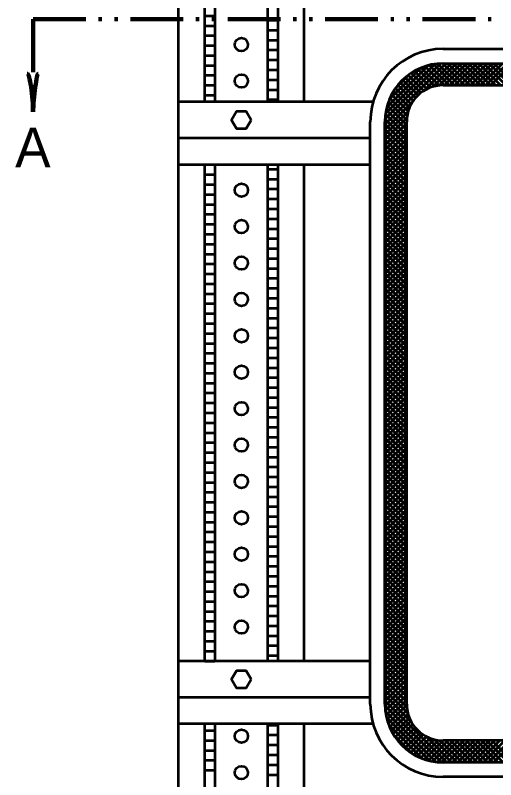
# Model space of a CAD drawing. Extents: x -87 to 768, y -466 to 78.
# Drawn here: x 252.4 to 296, y -292.3 to -223 of the extents above; entities that cross this region are included whole.
import ezdxf
from ezdxf.enums import TextEntityAlignment as Align

# ---------------------------------------------------------------- set-up
doc = ezdxf.new("R2010")
doc.units = 0
doc.header["$LTSCALE"] = 0.96
doc.linetypes.add('DASH_DOUBLE_DOT', pattern=[9.2, 5, -1.2, 0.3, -1.2, 0.3, -1.2])
doc.layers.add('1', color=7, linetype='Continuous', lineweight=53)

msp = doc.modelspace()

# ---------------------------------------------------------------- linework, layer by layer
at = {"layer": '1'}
for p, q in [((267.1887, -317.295), (267.1887, -172.4594)), ((269.5887, -230.895), (269.5887, -174.8594)), ((270.4887, -175.7593), (270.4887, -230.895)), ((275.2887, -230.895), (275.2887, -180.5593)), ((276.1887, -181.4593), (276.1887, -230.895)), ((278.5887, -230.895), (278.5887, -183.8593)), ((269.5887, -223.089), (270.4887, -223.089)), ((275.2887, -223.4938), (276.1887, -223.4938)), ((269.5887, -223.989), (270.4887, -223.989)), ((275.2887, -224.3938), (276.1887, -224.3938)), ((269.5887, -224.889), (270.4887, -224.889)), ((269.5887, -225.789), (270.4887, -225.789)), ((275.2887, -225.2938), (276.1887, -225.2938)), ((275.2887, -226.1938), (276.1887, -226.1938)), ((291.1887, -226.095), (343.9887, -226.095)), ((269.5887, -226.689), (270.4887, -226.689)), ((275.2887, -227.0938), (276.1887, -227.0938)), ((269.5887, -227.589), (270.4887, -227.589)), ((275.2887, -227.9938), (276.1887, -227.9938)), ((285.9087, -232.9502), (291.4439, -227.415)), ((285.9165, -232.4756), (290.9694, -227.4227)), ((285.9598, -231.9655), (290.4571, -227.4684)), ((286.0783, -231.3805), (289.8745, -227.5842)), ((286.3117, -230.6803), (289.1748, -227.8172)), ((290.4321, -229.4832), (288.8917, -227.9427)), ((290.8328, -229.4172), (289.2155, -227.7998)), ((289.4043, -229.9212), (291.9105, -227.415)), ((291.2772, -229.395), (289.5578, -227.6755)), ((291.744, -229.395), (289.9207, -227.5718)), ((290.2609, -229.5312), (292.3772, -227.415)), ((292.2107, -229.395), (290.3066, -227.491)), ((292.6773, -229.395), (290.7189, -227.4365)), ((290.8425, -229.4163), (292.8438, -227.415)), ((293.144, -229.395), (291.1643, -227.4152)), ((291.1887, -227.415), (343.9887, -227.415)), ((291.3306, -229.395), (293.3106, -227.415)), ((293.6107, -229.395), (291.6307, -227.415)), ((291.7973, -229.395), (293.7773, -227.415)), ((294.0774, -229.395), (292.0974, -227.415)), ((292.2639, -229.395), (294.2439, -227.415)), ((294.5441, -229.395), (292.5641, -227.415)), ((292.7307, -229.395), (294.7107, -227.415)), ((295.0107, -229.395), (293.0307, -227.415)), ((293.1974, -229.395), (295.1774, -227.415)), ((295.4775, -229.395), (293.4975, -227.415)), ((293.664, -229.395), (295.644, -227.415)), ((295.9442, -229.395), (293.9642, -227.415)), ((294.1307, -229.395), (296.1107, -227.415)), ((296.4108, -229.395), (294.4308, -227.415)), ((294.5975, -229.395), (296.5775, -227.415)), ((296.8775, -229.395), (294.8975, -227.415)), ((295.0641, -229.395), (297.0441, -227.415)), ((297.3443, -229.395), (295.3643, -227.415)), ((295.5308, -229.395), (297.5108, -227.415)), ((297.8109, -229.395), (295.8309, -227.415)), ((269.5887, -228.489), (270.4887, -228.489)), ((286.8856, -229.6398), (288.1306, -228.3947)), ((289.1695, -230.0874), (287.7626, -228.6804)), ((289.4453, -229.8964), (288.0211, -228.4723)), ((289.7461, -229.7306), (288.2945, -228.279)), ((290.074, -229.5919), (288.585, -228.1027)), ((275.2887, -228.8938), (276.1887, -228.8938)), ((288.6896, -230.5408), (287.289, -229.1402)), ((288.9175, -230.302), (287.5186, -228.9031)), ((269.5887, -229.389), (270.4887, -229.389)), ((275.2887, -229.7938), (276.1887, -229.7938)), ((288.1545, -231.4058), (286.6877, -229.939)), ((288.3074, -231.092), (286.8732, -229.6577)), ((288.4863, -230.8043), (287.0738, -229.3917)), ((291.1887, -229.395), (343.9887, -229.395)), ((269.5887, -230.289), (270.4887, -230.289)), ((275.2887, -230.6938), (276.1887, -230.6938)), ((287.9392, -232.1238), (286.3652, -230.5498)), ((288.03, -231.7481), (286.5181, -230.236)), ((284.8389, -230.895), (267.1887, -230.895)), ((285.9087, -233.4168), (288.4194, -230.906)), ((287.8887, -233.0067), (286.1154, -231.2335)), ((287.8953, -232.5467), (286.2303, -230.8817)), ((285.9087, -233.8835), (288.0233, -231.7688)), ((287.8887, -233.9402), (285.9554, -232.0069)), ((287.8887, -233.4734), (286.0227, -231.6075)), ((284.5887, -285.495), (284.5887, -232.695)), ((285.9087, -234.3501), (287.9086, -232.3502)), ((285.9087, -285.495), (285.9087, -232.695)), ((285.9087, -234.8169), (287.8887, -232.8369)), ((287.8887, -234.4068), (285.9178, -232.436)), ((287.8887, -285.495), (287.8887, -232.695)), ((287.8887, -234.8735), (285.9087, -232.8935)), ((285.9087, -235.2836), (287.8887, -233.3036)), ((287.8887, -235.3402), (285.9087, -233.3602)), ((284.5887, -234.195), (267.1887, -234.195)), ((285.9087, -235.7502), (287.8887, -233.7702)), ((287.8887, -235.8069), (285.9087, -233.8269)), ((285.9087, -236.2169), (287.8887, -234.2369)), ((287.8887, -236.2736), (285.9087, -234.2936)), ((285.9087, -236.6837), (287.8887, -234.7037)), ((287.8887, -236.7402), (285.9087, -234.7602)), ((285.9087, -237.1503), (287.8887, -235.1703)), ((287.8887, -237.2069), (285.9087, -235.2269)), ((285.9087, -237.617), (287.8887, -235.637)), ((287.8887, -237.6737), (285.9087, -235.6937)), ((285.9087, -238.0837), (287.8887, -236.1037)), ((287.8887, -238.1403), (285.9087, -236.1603)), ((284.5887, -236.595), (267.1887, -236.595)), ((269.5887, -281.595), (269.5887, -236.595)), ((270.4887, -236.595), (270.4887, -281.595)), ((275.2887, -281.595), (275.2887, -236.595)), ((275.2887, -236.9938), (276.1887, -236.9938)), ((276.1887, -236.595), (276.1887, -281.595)), ((278.5887, -281.595), (278.5887, -236.595)), ((285.9087, -238.5504), (287.8887, -236.5704)), ((287.8887, -238.607), (285.9087, -236.627)), ((269.5887, -237.489), (270.4887, -237.489)), ((285.9087, -239.0171), (287.8887, -237.0371)), ((287.8887, -239.0737), (285.9087, -237.0937)), ((285.9087, -239.4838), (287.8887, -237.5038)), ((287.8887, -239.5404), (285.9087, -237.5604)), ((269.5887, -238.389), (270.4887, -238.389)), ((275.2887, -237.8938), (276.1887, -237.8938)), ((285.9087, -239.9504), (287.8887, -237.9704)), ((287.8887, -240.0071), (285.9087, -238.0271)), ((275.2887, -238.7938), (276.1887, -238.7938)), ((285.9087, -240.4172), (287.8887, -238.4372)), ((287.8887, -240.4738), (285.9087, -238.4938)), ((285.9087, -240.8838), (287.8887, -238.9038)), ((287.8887, -240.9404), (285.9087, -238.9604)), ((269.5887, -239.289), (270.4887, -239.289)), ((275.2887, -239.6938), (276.1887, -239.6938)), ((285.9087, -241.3505), (287.8887, -239.3705)), ((287.8887, -241.4072), (285.9087, -239.4272)), ((269.5887, -240.189), (270.4887, -240.189)), ((285.9087, -241.8173), (287.8887, -239.8373)), ((287.8887, -241.8739), (285.9087, -239.8939)), ((285.9087, -242.2839), (287.8887, -240.3039)), ((287.8887, -242.3405), (285.9087, -240.3605)), ((269.5887, -241.089), (270.4887, -241.089)), ((275.2887, -240.5938), (276.1887, -240.5938)), ((285.9087, -242.7506), (287.8887, -240.7706)), ((287.8887, -242.8073), (285.9087, -240.8273)), ((275.2887, -241.4938), (276.1887, -241.4938)), ((285.9087, -243.2173), (287.8887, -241.2373)), ((287.8887, -243.2739), (285.9087, -241.2939)), ((285.9087, -243.684), (287.8887, -241.704)), ((287.8887, -243.7406), (285.9087, -241.7606)), ((269.5887, -241.989), (270.4887, -241.989)), ((275.2887, -242.3938), (276.1887, -242.3938)), ((285.9087, -244.1507), (287.8887, -242.1707)), ((287.8887, -244.2073), (285.9087, -242.2273)), ((269.5887, -242.889), (270.4887, -242.889)), ((285.9087, -244.6174), (287.8887, -242.6374)), ((287.8887, -244.674), (285.9087, -242.694)), ((285.9087, -245.084), (287.8887, -243.104)), ((287.8887, -245.1407), (285.9087, -243.1607)), ((269.5887, -243.789), (270.4887, -243.789)), ((275.2887, -243.2938), (276.1887, -243.2938)), ((285.9087, -245.5508), (287.8887, -243.5708)), ((287.8887, -245.6074), (285.9087, -243.6274)), ((275.2887, -244.1938), (276.1887, -244.1938)), ((285.9087, -246.0174), (287.8887, -244.0374)), ((287.8887, -246.074), (285.9087, -244.094)), ((285.9087, -246.4841), (287.8887, -244.5041)), ((287.8887, -246.5408), (285.9087, -244.5608)), ((269.5887, -244.689), (270.4887, -244.689)), ((275.2887, -245.0938), (276.1887, -245.0938)), ((285.9087, -246.9508), (287.8887, -244.9708)), ((287.8887, -247.0075), (285.9087, -245.0275)), ((269.5887, -245.589), (270.4887, -245.589)), ((275.2887, -245.9938), (276.1887, -245.9938)), ((285.9087, -247.4175), (287.8887, -245.4375)), ((287.8887, -247.4741), (285.9087, -245.4941)), ((285.9087, -247.8842), (287.8887, -245.9042)), ((287.8887, -247.9408), (285.9087, -245.9608)), ((269.5887, -246.489), (270.4887, -246.489)), ((285.9087, -248.3509), (287.8887, -246.3709)), ((287.8887, -248.4075), (285.9087, -246.4275)), ((269.5887, -247.389), (270.4887, -247.389)), ((275.2887, -246.8938), (276.1887, -246.8938)), ((285.9087, -248.8175), (287.8887, -246.8375)), ((287.8887, -248.8742), (285.9087, -246.8942)), ((285.9087, -249.2843), (287.8887, -247.3043)), ((287.8887, -249.3409), (285.9087, -247.3609)), ((275.2887, -247.7938), (276.1887, -247.7938)), ((285.9087, -249.751), (287.8887, -247.771)), ((287.8887, -249.8075), (285.9087, -247.8275)), ((269.5887, -248.289), (270.4887, -248.289)), ((275.2887, -248.6938), (276.1887, -248.6938)), ((285.9087, -250.2176), (287.8887, -248.2376)), ((287.8887, -250.2743), (285.9087, -248.2943)), ((285.9087, -250.6844), (287.8887, -248.7044)), ((287.8887, -250.741), (285.9087, -248.761)), ((269.5887, -249.189), (270.4887, -249.189)), ((285.9087, -251.1511), (287.8887, -249.1711)), ((287.8887, -251.2076), (285.9087, -249.2276)), ((269.5887, -250.089), (270.4887, -250.089)), ((275.2887, -249.5938), (276.1887, -249.5938)), ((285.9087, -251.6177), (287.8887, -249.6377)), ((287.8887, -251.6744), (285.9087, -249.6944)), ((285.9087, -252.0844), (287.8887, -250.1044)), ((287.8887, -252.1411), (285.9087, -250.1611)), ((275.2887, -250.4938), (276.1887, -250.4938)), ((285.9087, -252.5511), (287.8887, -250.5711)), ((287.8887, -252.6077), (285.9087, -250.6277)), ((269.5887, -250.989), (270.4887, -250.989)), ((275.2887, -251.3938), (276.1887, -251.3938)), ((285.9087, -253.0178), (287.8887, -251.0378)), ((287.8887, -253.0744), (285.9087, -251.0944)), ((285.9087, -253.4845), (287.8887, -251.5045)), ((269.5887, -251.889), (270.4887, -251.889)), ((287.8887, -253.5412), (285.9087, -251.5612)), ((285.9087, -253.9511), (287.8887, -251.9711)), ((287.8887, -254.0078), (285.9087, -252.0278)), ((269.5887, -252.789), (270.4887, -252.789)), ((275.2887, -252.2938), (276.1887, -252.2938)), ((285.9087, -254.4179), (287.8887, -252.4379)), ((287.8887, -254.4745), (285.9087, -252.4945)), ((285.9087, -254.8846), (287.8887, -252.9046)), ((275.2887, -253.1938), (276.1887, -253.1938)), ((287.8887, -254.9411), (285.9087, -252.9611)), ((285.9087, -255.3512), (287.8887, -253.3712)), ((287.8887, -255.4079), (285.9087, -253.4279)), ((269.5887, -253.689), (270.4887, -253.689)), ((275.2887, -254.0938), (276.1887, -254.0938)), ((285.9087, -255.8179), (287.8887, -253.8379)), ((287.8887, -255.8746), (285.9087, -253.8946)), ((285.9087, -256.2847), (287.8887, -254.3047)), ((269.5887, -254.589), (270.4887, -254.589)), ((275.2887, -254.9938), (276.1887, -254.9938)), ((287.8887, -256.3412), (285.9087, -254.3612)), ((285.9087, -256.7513), (287.8887, -254.7713)), ((287.8887, -256.8079), (285.9087, -254.8279)), ((269.5887, -255.489), (270.4887, -255.489)), ((285.9087, -257.218), (287.8887, -255.238)), ((287.8887, -257.2747), (285.9087, -255.2947)), ((285.9087, -257.6846), (287.8887, -255.7046)), ((269.5887, -256.389), (270.4887, -256.389)), ((275.2887, -255.8938), (276.1887, -255.8938)), ((287.8887, -257.7413), (285.9087, -255.7613)), ((285.9087, -258.1514), (287.8887, -256.1714)), ((287.8887, -258.208), (285.9087, -256.228)), ((275.2887, -256.7938), (276.1887, -256.7938)), ((285.9087, -258.6181), (287.8887, -256.6381)), ((287.8887, -258.6748), (285.9087, -256.6948)), ((269.5887, -257.289), (270.4887, -257.289)), ((275.2887, -257.6938), (276.1887, -257.6938)), ((285.9087, -259.0847), (287.8887, -257.1047)), ((287.8887, -259.1414), (285.9087, -257.1614)), ((285.9087, -259.5515), (287.8887, -257.5715)), ((287.8887, -259.6081), (285.9087, -257.6281)), ((269.5887, -258.189), (270.4887, -258.189)), ((285.9087, -260.0182), (287.8887, -258.0382)), ((287.8887, -260.0747), (285.9087, -258.0947)), ((269.5887, -259.089), (270.4887, -259.089)), ((275.2887, -258.5938), (276.1887, -258.5938)), ((285.9087, -260.4848), (287.8887, -258.5048)), ((287.8887, -260.5415), (285.9087, -258.5615)), ((285.9087, -260.9515), (287.8887, -258.9715)), ((287.8887, -261.0082), (285.9087, -259.0282)), ((275.2887, -259.4938), (276.1887, -259.4938)), ((285.9087, -261.4183), (287.8887, -259.4383)), ((287.8887, -261.4748), (285.9087, -259.4948)), ((269.5887, -259.989), (270.4887, -259.989)), ((275.2887, -260.3938), (276.1887, -260.3938)), ((285.9087, -261.8849), (287.8887, -259.9049)), ((287.8887, -261.9415), (285.9087, -259.9615)), ((285.9087, -262.3516), (287.8887, -260.3716)), ((287.8887, -262.4083), (285.9087, -260.4283)), ((269.5887, -260.889), (270.4887, -260.889)), ((285.9087, -262.8183), (287.8887, -260.8383)), ((287.8887, -262.8749), (285.9087, -260.8949)), ((269.5887, -261.789), (270.4887, -261.789)), ((275.2887, -261.2938), (276.1887, -261.2938)), ((285.9087, -263.285), (287.8887, -261.305)), ((287.8887, -263.3416), (285.9087, -261.3616)), ((285.9087, -263.7517), (287.8887, -261.7717)), ((287.8887, -263.8083), (285.9087, -261.8283)), ((275.2887, -262.1938), (276.1887, -262.1938)), ((285.9087, -264.2183), (287.8887, -262.2383)), ((287.8887, -264.275), (285.9087, -262.295)), ((269.5887, -262.689), (270.4887, -262.689)), ((275.2887, -263.0938), (276.1887, -263.0938)), ((285.9087, -264.685), (287.8887, -262.705)), ((287.8887, -264.7417), (285.9087, -262.7617)), ((285.9087, -265.1518), (287.8887, -263.1718)), ((287.8887, -265.2084), (285.9087, -263.2284)), ((269.5887, -263.589), (270.4887, -263.589)), ((275.2887, -263.9938), (276.1887, -263.9938)), ((285.9087, -265.6184), (287.8887, -263.6384)), ((287.8887, -265.675), (285.9087, -263.695)), ((269.5887, -264.489), (270.4887, -264.489)), ((285.9087, -266.0851), (287.8887, -264.1051)), ((287.8887, -266.1418), (285.9087, -264.1618)), ((285.9087, -266.5519), (287.8887, -264.5719)), ((287.8887, -266.6084), (285.9087, -264.6284)), ((269.5887, -265.389), (270.4887, -265.389)), ((275.2887, -264.8938), (276.1887, -264.8938)), ((285.9087, -267.0185), (287.8887, -265.0385)), ((287.8887, -267.0751), (285.9087, -265.0951)), ((275.2887, -265.7938), (276.1887, -265.7938)), ((285.9087, -267.4852), (287.8887, -265.5052)), ((287.8887, -267.5419), (285.9087, -265.5619)), ((285.9087, -267.9519), (287.8887, -265.9719)), ((287.8887, -268.0085), (285.9087, -266.0285)), ((269.5887, -266.289), (270.4887, -266.289)), ((275.2887, -266.6938), (276.1887, -266.6938)), ((285.9087, -268.4186), (287.8887, -266.4386)), ((287.8887, -268.4752), (285.9087, -266.4952)), ((269.5887, -267.189), (270.4887, -267.189)), ((285.9087, -268.8853), (287.8887, -266.9053)), ((287.8887, -268.9419), (285.9087, -266.9619)), ((285.9087, -269.352), (287.8887, -267.372)), ((287.8887, -269.4086), (285.9087, -267.4286)), ((269.5887, -268.089), (270.4887, -268.089)), ((275.2887, -267.5938), (276.1887, -267.5938)), ((285.9087, -269.8186), (287.8887, -267.8386)), ((287.8887, -269.8753), (285.9087, -267.8953)), ((275.2887, -268.4938), (276.1887, -268.4938)), ((285.9087, -270.2854), (287.8887, -268.3054)), ((287.8887, -270.342), (285.9087, -268.362)), ((285.9087, -270.752), (287.8887, -268.772)), ((287.8887, -270.8086), (285.9087, -268.8286)), ((269.5887, -268.989), (270.4887, -268.989)), ((275.2887, -269.3938), (276.1887, -269.3938)), ((285.9087, -271.2187), (287.8887, -269.2387)), ((287.8887, -271.2754), (285.9087, -269.2954)), ((269.5887, -269.889), (270.4887, -269.889)), ((285.9087, -271.6854), (287.8887, -269.7054)), ((287.8887, -271.7421), (285.9087, -269.7621)), ((285.9087, -272.1521), (287.8887, -270.1721)), ((287.8887, -272.2087), (285.9087, -270.2287)), ((269.5887, -270.789), (270.4887, -270.789)), ((275.2887, -270.2938), (276.1887, -270.2938)), ((285.9087, -272.6188), (287.8887, -270.6388)), ((287.8887, -272.6754), (285.9087, -270.6954)), ((275.2887, -271.1938), (276.1887, -271.1938)), ((285.9087, -273.0855), (287.8887, -271.1055)), ((287.8887, -273.1421), (285.9087, -271.1621)), ((285.9087, -273.5521), (287.8887, -271.5721)), ((287.8887, -273.6088), (285.9087, -271.6288)), ((269.5887, -271.689), (270.4887, -271.689)), ((275.2887, -272.0938), (276.1887, -272.0938)), ((285.9087, -274.0189), (287.8887, -272.0389)), ((287.8887, -274.0755), (285.9087, -272.0955)), ((269.5887, -272.589), (270.4887, -272.589)), ((275.2887, -272.9938), (276.1887, -272.9938)), ((285.9087, -274.4856), (287.8887, -272.5056)), ((287.8887, -274.5421), (285.9087, -272.5621)), ((285.9087, -274.9522), (287.8887, -272.9722)), ((287.8887, -275.0089), (285.9087, -273.0289)), ((269.5887, -273.489), (270.4887, -273.489)), ((285.9087, -275.419), (287.8887, -273.439)), ((287.8887, -275.4756), (285.9087, -273.4956)), ((269.5887, -274.389), (270.4887, -274.389)), ((275.2887, -273.8938), (276.1887, -273.8938)), ((285.9087, -275.8856), (287.8887, -273.9056)), ((287.8887, -275.9422), (285.9087, -273.9622)), ((285.9087, -276.3523), (287.8887, -274.3723)), ((275.2887, -274.7938), (276.1887, -274.7938)), ((287.8887, -276.409), (285.9087, -274.429)), ((285.9087, -276.819), (287.8887, -274.839)), ((287.8887, -276.8757), (285.9087, -274.8957)), ((269.5887, -275.289), (270.4887, -275.289)), ((275.2887, -275.6938), (276.1887, -275.6938)), ((285.9087, -277.2857), (287.8887, -275.3057)), ((287.8887, -277.3423), (285.9087, -275.3623)), ((285.9087, -277.7524), (287.8887, -275.7724)), ((269.5887, -276.189), (270.4887, -276.189)), ((287.8887, -277.809), (285.9087, -275.829)), ((285.9087, -278.2191), (287.8887, -276.2391)), ((287.8887, -278.2757), (285.9087, -276.2957)), ((269.5887, -277.089), (270.4887, -277.089)), ((275.2887, -276.5938), (276.1887, -276.5938)), ((285.9087, -278.6857), (287.8887, -276.7057)), ((287.8887, -278.7424), (285.9087, -276.7624)), ((285.9087, -279.1525), (287.8887, -277.1725)), ((275.2887, -277.4938), (276.1887, -277.4938)), ((287.8887, -279.2091), (285.9087, -277.2291)), ((285.9087, -279.6192), (287.8887, -277.6392)), ((287.8887, -279.6757), (285.9087, -277.6957)), ((269.5887, -277.989), (270.4887, -277.989)), ((275.2887, -278.3938), (276.1887, -278.3938)), ((285.9087, -280.0858), (287.8887, -278.1058)), ((287.8887, -280.1425), (285.9087, -278.1625)), ((285.9087, -280.5525), (287.8887, -278.5725)), ((269.5887, -278.889), (270.4887, -278.889)), ((287.8887, -280.6092), (285.9087, -278.6292)), ((285.9087, -281.0193), (287.8887, -279.0393)), ((287.8887, -281.0758), (285.9087, -279.0958)), ((269.5887, -279.789), (270.4887, -279.789)), ((275.2887, -279.2938), (276.1887, -279.2938)), ((285.9087, -281.4859), (287.8887, -279.5059)), ((287.8887, -281.5425), (285.9087, -279.5625)), ((275.2887, -280.1938), (276.1887, -280.1938)), ((285.9087, -281.9526), (287.8887, -279.9726)), ((287.8887, -282.0093), (285.9087, -280.0293)), ((285.9087, -282.4192), (287.8887, -280.4392)), ((287.8887, -282.4759), (285.9087, -280.4959)), ((269.5887, -280.689), (270.4887, -280.689)), ((275.2887, -281.0938), (276.1887, -281.0938)), ((285.9087, -282.886), (287.8887, -280.906)), ((287.8887, -282.9426), (285.9087, -280.9626)), ((284.5887, -281.595), (267.1887, -281.595)), ((269.5887, -281.589), (270.4887, -281.589)), ((285.9087, -283.3527), (287.8887, -281.3727)), ((287.8887, -283.4094), (285.9087, -281.4294)), ((285.9087, -283.8193), (287.8887, -281.8393)), ((287.8887, -283.876), (285.9087, -281.896)), ((285.9087, -284.2861), (287.8887, -282.3061)), ((287.8887, -284.3427), (285.9087, -282.3627)), ((285.9087, -284.7528), (287.8887, -282.7728)), ((287.8887, -284.8093), (285.9087, -282.8293)), ((285.9087, -285.2194), (287.8887, -283.2394)), ((287.8887, -285.2761), (285.9087, -283.2961)), ((287.9019, -285.756), (285.9087, -283.7628)), ((285.9146, -285.6802), (287.8887, -283.7061)), ((287.9949, -286.3157), (285.9087, -284.2294)), ((288.2984, -287.0859), (285.9087, -284.6961)), ((285.9483, -286.1133), (287.8887, -284.1729)), ((286.0117, -286.5164), (287.8887, -284.6395)), ((284.5887, -284.895), (267.1887, -284.895)), ((291.5208, -290.775), (285.9087, -285.1629)), ((286.1007, -286.8942), (287.8887, -285.1062)), ((291.0492, -290.77), (285.9122, -285.6331)), ((290.5455, -290.733), (285.9515, -286.139)), ((286.2122, -287.2495), (287.8905, -285.571)), ((286.3434, -287.5848), (287.9292, -285.9991)), ((289.9771, -290.6314), (286.0496, -286.7039)), ((286.493, -287.902), (288.0134, -286.3816)), ((286.6593, -288.2023), (288.1314, -286.7303)), ((284.8389, -287.295), (267.1887, -287.295)), ((269.5887, -317.295), (269.5887, -287.295)), ((270.4887, -287.295), (270.4887, -317.295)), ((275.2887, -317.295), (275.2887, -287.295)), ((275.2887, -287.3938), (276.1887, -287.3938)), ((276.1887, -287.295), (276.1887, -317.295)), ((278.5887, -317.295), (278.5887, -287.295)), ((289.3045, -290.4254), (286.2564, -287.3773)), ((286.8416, -288.4867), (288.2788, -287.0495)), ((287.0389, -288.7561), (288.4543, -287.3408)), ((269.5887, -287.889), (270.4887, -287.889)), ((287.2509, -289.0108), (288.6554, -287.6064)), ((287.4778, -289.2506), (288.8798, -287.8486)), ((287.7207, -289.4743), (289.1274, -288.0677)), ((287.9781, -289.6836), (289.3984, -288.2633)), ((269.5887, -288.789), (270.4887, -288.789)), ((275.2887, -288.2938), (276.1887, -288.2938)), ((288.3737, -289.9613), (286.7282, -288.3158)), ((288.2502, -289.8781), (289.6942, -288.4343)), ((288.5377, -290.0574), (290.0163, -288.5789)), ((288.8412, -290.2207), (290.3718, -288.69)), ((289.1617, -290.3669), (290.7643, -288.7643)), ((289.5007, -290.4946), (291.2002, -288.795)), ((291.9875, -290.775), (289.5921, -288.3796)), ((289.8601, -290.6018), (291.667, -288.795)), ((290.2425, -290.6862), (292.1337, -288.795)), ((292.4542, -290.775), (290.3685, -288.6894)), ((290.6511, -290.7443), (292.6003, -288.795)), ((292.9208, -290.775), (290.9293, -288.7833)), ((291.0906, -290.7714), (293.067, -288.795)), ((343.9887, -288.795), (291.1887, -288.795)), ((293.3876, -290.775), (291.4076, -288.795)), ((291.5538, -290.775), (293.5338, -288.795)), ((293.8543, -290.775), (291.8743, -288.795)), ((292.0204, -290.775), (294.0004, -288.795)), ((294.3209, -290.775), (292.3409, -288.795)), ((292.4871, -290.775), (294.4671, -288.795)), ((294.7877, -290.775), (292.8077, -288.795)), ((292.9538, -290.775), (294.9338, -288.795)), ((295.2543, -290.775), (293.2743, -288.795)), ((293.4205, -290.775), (295.4005, -288.795)), ((295.721, -290.775), (293.741, -288.795)), ((293.8872, -290.775), (295.8672, -288.795)), ((296.1877, -290.775), (294.2077, -288.795)), ((294.3539, -290.775), (296.3339, -288.795)), ((296.6544, -290.775), (294.6744, -288.795)), ((294.8205, -290.775), (296.8005, -288.795)), ((297.1211, -290.775), (295.1411, -288.795)), ((295.2873, -290.775), (297.2673, -288.795)), ((297.5878, -290.775), (295.6078, -288.795)), ((295.7539, -290.775), (297.7339, -288.795)), ((275.2887, -289.1938), (276.1887, -289.1938)), ((269.5887, -289.689), (270.4887, -289.689)), ((275.2887, -290.0938), (276.1887, -290.0938)), ((269.5887, -290.589), (270.4887, -290.589)), ((275.2887, -290.9938), (276.1887, -290.9938)), ((343.9887, -290.775), (291.1887, -290.775)), ((269.5887, -291.489), (270.4887, -291.489)), ((275.2887, -291.8938), (276.1887, -291.8938)), ((343.9887, -292.095), (291.1887, -292.095))]:
    msp.add_line(p, q, dxfattribs=at)
at = {"layer": '1', "linetype": 'DASH_DOUBLE_DOT', "lineweight": 106}
for q in [(381.1887, -223.395), (253.9887, -231.795)]:
    msp.add_line((253.9887, -223.395), q, dxfattribs=at)
at = {"layer": '1'}
for points in [[(273.7887, -232.545), (273.3387, -231.7656), (272.4387, -231.7656), (271.9887, -232.545), (272.4387, -233.3244), (273.3387, -233.3244)], [(273.7887, -283.245), (273.3387, -282.4656), (272.4387, -282.4656), (271.9887, -283.245), (272.4387, -284.0244), (273.3387, -284.0244)]]:
    msp.add_lwpolyline(points, close=True, dxfattribs=at)
for centre in [(272.8887, -225.7057), (272.8887, -229.0057), (272.8887, -238.9057), (272.8887, -242.2057), (272.8887, -245.5057), (272.8887, -248.8057), (272.8887, -252.1057), (272.8887, -255.4057), (272.8887, -258.7057), (272.8887, -262.0057), (272.8887, -265.3057), (272.8887, -268.6057), (272.8887, -271.9057), (272.8887, -275.2057), (272.8887, -278.5057), (272.8887, -288.4057), (272.8887, -291.7057)]:
    msp.add_circle(centre, 0.6, dxfattribs=at)
for centre, radius, start, end in [((291.1887, -232.695), 6.6, 90, 180), ((291.1887, -232.695), 5.28, 90, 180), ((291.1887, -232.695), 3.3, 90, 180), ((291.1887, -285.495), 6.6, 180, 270), ((291.1887, -285.495), 5.28, 180, 270), ((291.1887, -285.495), 3.3, 180, 270)]:
    msp.add_arc(centre, radius, start, end, dxfattribs=at)
at = {"layer": '1', "lineweight": 106}
for centre, major_axis, ratio, start_param, end_param in [((253.6571, -230.4856), (0.1874, -2.1428), 0.122415, 0.8963533, 3.1415927), ((254.2426, -230.4504), (-0.2108, -2.1077), 0.07063, 3.1407148, 5.41811)]:
    msp.add_ellipse(centre, major_axis=major_axis, ratio=ratio, start_param=start_param, end_param=end_param, dxfattribs=at)

# ---------------------------------------------------------------- texts
at = {"layer": '1'}
msp.add_text('A', height=3.6, dxfattribs=at).set_placement((253.9748, -236.822), align=Align.CENTER)

doc.saveas('drawing.dxf')
